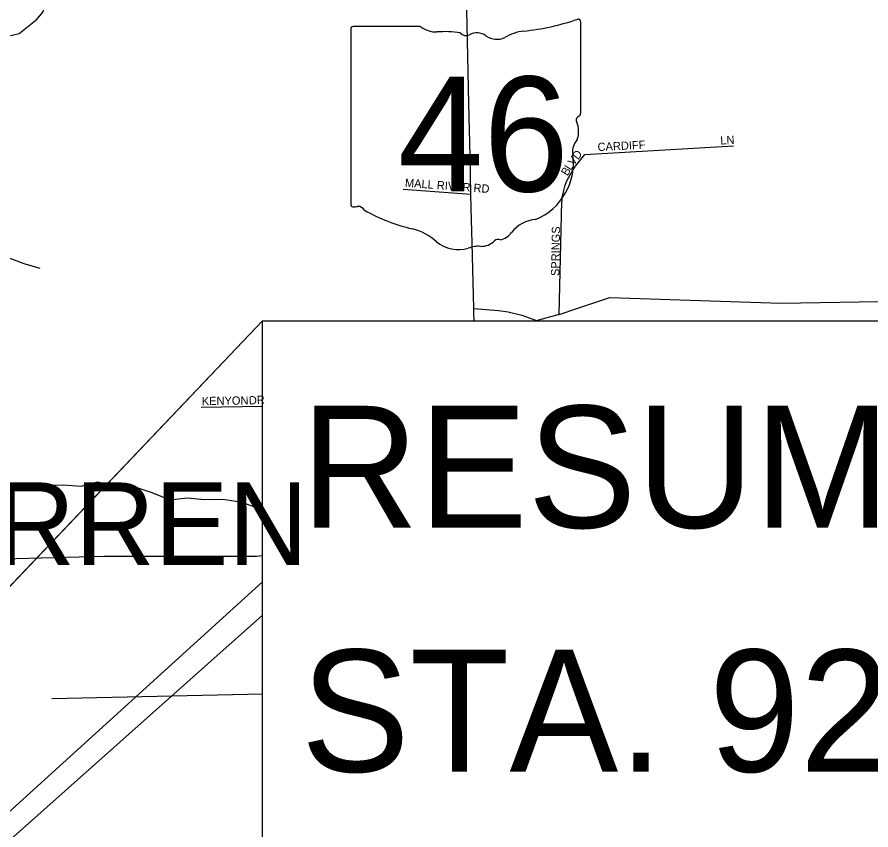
# Model space of a CAD drawing. Extents: x -37878.7 to -37844.7, y -19791.4 to -19769.4.
# Drawn here: x -37872 to -37871.021, y -19773.183 to -19772.25 of the extents above; entities that cross this region are included whole.
import ezdxf

# ---------------------------------------------------------------- set-up
doc = ezdxf.new("R2010")
doc.units = 0
for name, color, linetype in [('GM_X_Corporation_Text', 7, 'Continuous'), ('GM_X_Major_River', 7, 'Continuous'), ('GM_X_Minor_River', 7, 'Continuous'), ('GM_X_State_Route', 7, 'Continuous'), ('GM_X_State_Shield', 7, 'Continuous'), ('GM_X_Township_Road', 7, 'Continuous'), ('GM_X_Township_Subdivision', 7, 'Continuous'), ('GM_X_Township_Subdivision_Text', 7, 'Continuous'), ('TX_P_1', 7, 'Continuous')]:
    doc.layers.add(name, color=color, linetype=linetype)

msp = doc.modelspace()

# ---------------------------------------------------------------- linework, layer by layer
at = {"layer": 'GM_X_Major_River'}
for points in [[(-37871.97877, -19772.25369), (-37871.97052, -19772.24397), (-37871.96754, -19772.23031), (-37871.97127, -19772.22156), (-37871.9797, -19772.20891)], [(-37871.97877, -19772.25369), (-37871.99777, -19772.26928), (-37872.01738, -19772.27387)]]:
    msp.add_lwpolyline(points, dxfattribs=at)
at = {"layer": 'GM_X_Minor_River'}
for points in [[(-37872.15712, -19772.58625), (-37872.14842, -19772.56708), (-37872.1492, -19772.54812), (-37872.12996, -19772.54429), (-37872.11092, -19772.54844), (-37872.09083, -19772.53093), (-37872.07115, -19772.53013), (-37872.05209, -19772.5358), (-37872.03136, -19772.53042), (-37872.01177, -19772.52545), (-37871.99268, -19772.53263), (-37871.97438, -19772.53794)], [(-37871.96577, -19772.78716), (-37871.98583, -19772.7863), (-37871.99835, -19772.79004)], [(-37871.96577, -19772.78716), (-37871.94761, -19772.78688), (-37871.92679, -19772.78811), (-37871.90783, -19772.78327), (-37871.88628, -19772.78869), (-37871.86622, -19772.78878), (-37871.84581, -19772.79571), (-37871.82504, -19772.80417), (-37871.80496, -19772.8016), (-37871.78566, -19772.8036), (-37871.76446, -19772.80332), (-37871.74441, -19772.80645), (-37871.72514, -19772.81262), (-37871.71882, -19772.81608)], [(-37871.96052, -19773.03219), (-37871.71882, -19773.02663)]]:
    msp.add_lwpolyline(points, dxfattribs=at)
at = {"layer": 'GM_X_State_Route'}
for points in [[(-37871.48426, -19772.25914), (-37871.4854, -19772.20912), (-37871.48554, -19772.20324), (-37871.48572, -19772.19524), (-37871.48578, -19772.19253), (-37871.48639, -19772.16575)], [(-37871.48219, -19772.34918), (-37871.48426, -19772.25914)], [(-37871.48151, -19772.37919), (-37871.48219, -19772.34918)], [(-37871.48082, -19772.40921), (-37871.48151, -19772.37919)], [(-37871.4794, -19772.46923), (-37871.47981, -19772.45321), (-37871.48082, -19772.40921)], [(-37871.47838, -19772.50925), (-37871.4794, -19772.46923)], [(-37871.47684, -19772.56927), (-37871.47838, -19772.50925)], [(-37871.47635, -19772.58928), (-37871.47645, -19772.58423), (-37871.47684, -19772.56927)], [(-37871.47616, -19772.5985), (-37871.47635, -19772.58928)]]:
    msp.add_lwpolyline(points, dxfattribs=at)
at = {"layer": 'GM_X_State_Shield'}
for p, q in [((-37871.35388, -19772.36037), (-37871.35388, -19772.25568)), ((-37871.61754, -19772.26408), (-37871.61754, -19772.4642)), ((-37871.53773, -19772.26064), (-37871.61495, -19772.26064)), ((-37871.3539, -19772.36034), (-37871.35388, -19772.36037))]:
    msp.add_line(p, q, dxfattribs=at)
for centre, radius, start, end in [((-37871.4478, -19771.98781), 0.27961, 275.84447, 288.90645), ((-37871.3568, -19772.25525), 0.00294, 351.86209, 97.738), ((-37871.61452, -19772.26366), 0.00305, 98.1301, 188.1301), ((-37871.51934, -19772.23741), 0.02963, 231.61951, 271.11188), ((-37871.50952, -19772.37299), 0.10636, 80.48669, 94.98827), ((-37871.41213, -19772.32176), 0.05625, 97.34618, 120.76885), ((-37871.48537, -19772.26262), 0.00855, 219.79206, 297.10237), ((-37871.47282, -19772.28575), 0.01777, 54.46668, 119.14113), ((-37871.44989, -19772.25403), 0.02138, 233.85621, 294.82819), ((-37871.35455, -19772.36805), 0.00454, 107.94398, 210.33697), ((-37871.35701, -19772.36077), 0.00314, 289.60381, 7.73413), ((-37871.38345, -19772.38128), 0.02727, 340.03296, 23.64957), ((-37871.34336, -19772.40418), 0.01984, 136.8065, 186.92959), ((-37871.43213, -19772.41749), 0.06994, 292.30889, 8.98584), ((-37871.61449, -19772.46464), 0.00308, 171.95839, 258.30661), ((-37871.61403, -19772.44417), 0.02352, 267.33899, 280.60386), ((-37871.60921, -19772.47575), 0.00848, 29.74838, 93.27175), ((-37871.50215, -19772.29595), 0.20192, 240.41292, 257.1985), ((-37871.40264, -19772.52039), 0.0383, 94.40312, 142.57675), ((-37871.56235, -19772.55411), 0.06318, 47.18416, 75.83597), ((-37871.45117, -19772.4836), 0.0226, 282.87319, 323.27711), ((-37871.49403, -19772.47674), 0.04009, 230.70037, 286.29184), ((-37871.46793, -19772.49173), 0.02136, 268.77702, 315.54927), ((-37871.44861, -19772.51111), 0.00601, 65.75173, 132.64842), ((-37871.47086, -19772.54593), 0.03294, 85.69512, 111.20995)]:
    msp.add_arc(centre, radius, start, end, dxfattribs=at)
at = {"layer": 'GM_X_Township_Road'}
msp.add_lwpolyline([(-37871.47645, -19772.58423), (-37871.44829, -19772.58676), (-37871.43689, -19772.58803), (-37871.42138, -19772.59215), (-37871.4046, -19772.59816), (-37871.37964, -19772.59139), (-37871.3787, -19772.59109), (-37871.35816, -19772.58438), (-37871.32041, -19772.57188), (-37871.12429, -19772.57841), (-37870.98944, -19772.57579), (-37870.95247, -19772.57861), (-37870.84018, -19772.57656)], dxfattribs=at)
at = {"layer": 'GM_X_Township_Subdivision'}
for points in [[(-37871.34921, -19772.40761), (-37871.17851, -19772.39755)], [(-37871.3753, -19772.46065), (-37871.37528, -19772.46002), (-37871.37509, -19772.457), (-37871.37332, -19772.44906), (-37871.37178, -19772.44268), (-37871.36932, -19772.43723), (-37871.36339, -19772.42637), (-37871.3599, -19772.4212), (-37871.34921, -19772.40761)], [(-37871.5574, -19772.44752), (-37871.47981, -19772.45321)], [(-37871.3787, -19772.59109), (-37871.37531, -19772.46102), (-37871.3753, -19772.46065)], [(-37871.78924, -19772.69772), (-37871.71882, -19772.69636)], [(-37871.71882, -19772.8683), (-37871.72571, -19772.86921), (-37871.90047, -19772.86911), (-37872.14573, -19772.87537)]]:
    msp.add_lwpolyline(points, dxfattribs=at)
at = {"layer": 'TX_P_1'}
for p, q in [((-37871.71882, -19772.5985), (-37873.82258, -19774.8103)), ((-37871.71882, -19772.5985), (-37869.74005, -19772.5985)), ((-37871.71882, -19773.19753), (-37871.71882, -19772.5985)), ((-37873.82258, -19774.8103), (-37871.71882, -19772.89801))]:
    msp.add_line(p, q, dxfattribs=at)
msp.add_lwpolyline([(-37871.71882, -19772.5985), (-37873.82258, -19774.8103), (-37871.71882, -19772.93626)], close=True, dxfattribs=at)

# ---------------------------------------------------------------- texts
at = {"layer": 'GM_X_Corporation_Text'}
msp.add_text('WARREN', height=0.094696, rotation=0.00001, dxfattribs=at).set_placement((-37872.22929, -19772.87872))
at = {"layer": 'GM_X_State_Shield'}
msp.add_text('46', height=0.131836, dxfattribs=at).set_placement((-37871.56356, -19772.45009))
at = {"layer": 'GM_X_Township_Subdivision_Text'}
for s, height, rotation, p in [('CARDIFF', 0.00947, 2.91099, (-37871.33426, -19772.40376)), ('LN', 0.00947, 3.17848, (-37871.19344, -19772.39627)), ('D', 0.00947, 52.60995, (-37871.35689, -19772.41438)), ('V', 0.00947, 53.99351, (-37871.36175, -19772.42107)), ('B', 0.00947, 58.89047, (-37871.36904, -19772.43297)), ('L', 0.00947, 58.03805, (-37871.36518, -19772.42658)), ('MALL RIVER RD', 0.0094696, 355.72441, (-37871.55571, -19772.4446)), ('SPRINGS', 0.00947, 88.99548, (-37871.37846, -19772.54718)), ('KENYON', 0.00947, 0.97237, (-37871.78837, -19772.69543)), ('DR', 0.00947, 3.01098, (-37871.73427, -19772.6946))]:
    msp.add_text(s, height=height, rotation=rotation, dxfattribs=at).set_placement(p)
at = {"layer": 'TX_P_1'}
for s, p in [('RESUME PROJECT', (-37871.67482, -19772.83608)), ('STA. 92+50.00', (-37871.67482, -19773.11608))]:
    msp.add_text(s, height=0.14, rotation=360, dxfattribs=at).set_placement(p)

doc.saveas('drawing.dxf')
